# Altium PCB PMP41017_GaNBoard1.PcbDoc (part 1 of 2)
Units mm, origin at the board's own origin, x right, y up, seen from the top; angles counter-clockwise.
Board outline 21.11 x 35.1 mm, 4 copper layers (Top Layer, Layer 1, Layer 2, Bottom Layer), stack 1.926 mm thick; 24 components, 34 nets, 167 pads, 758 vias.
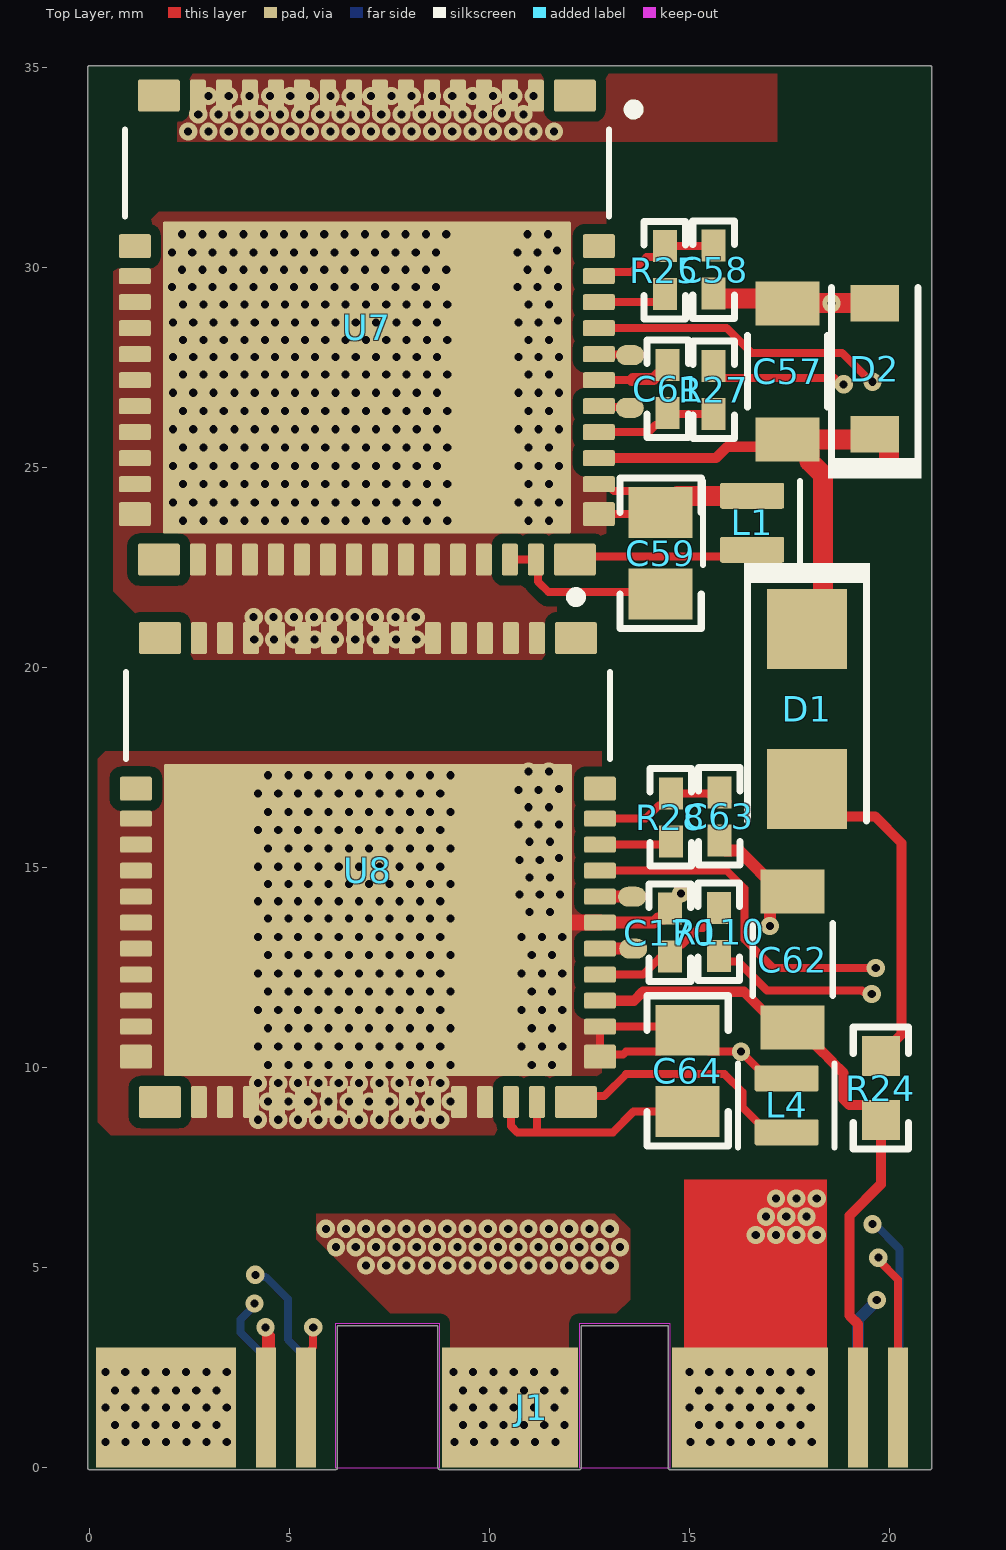
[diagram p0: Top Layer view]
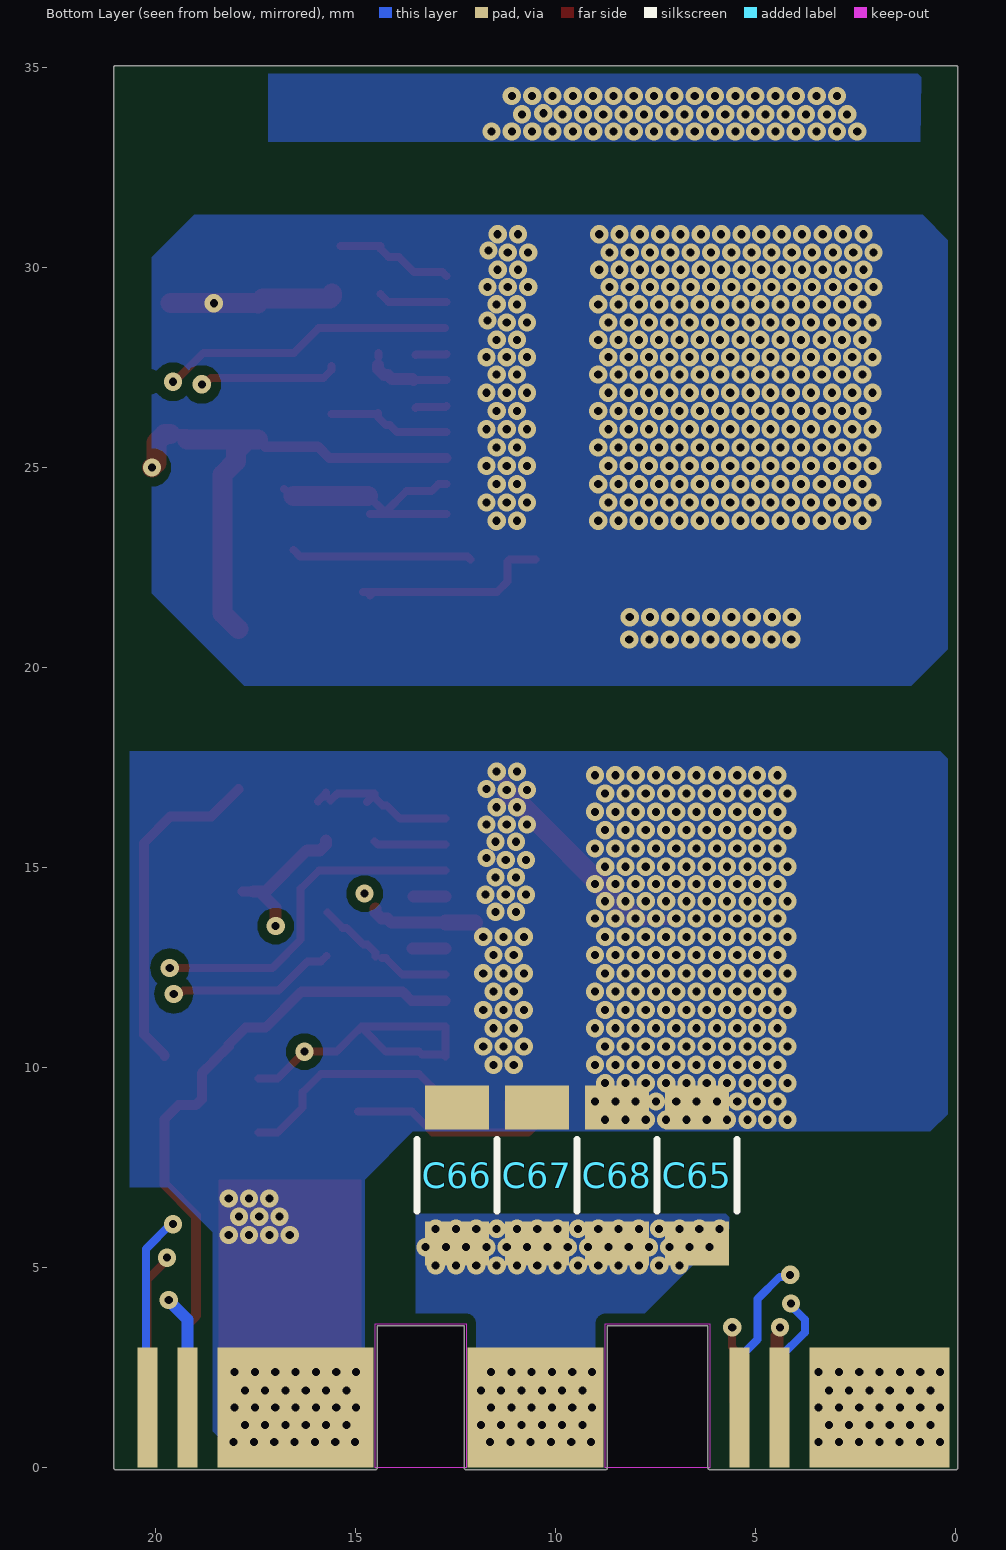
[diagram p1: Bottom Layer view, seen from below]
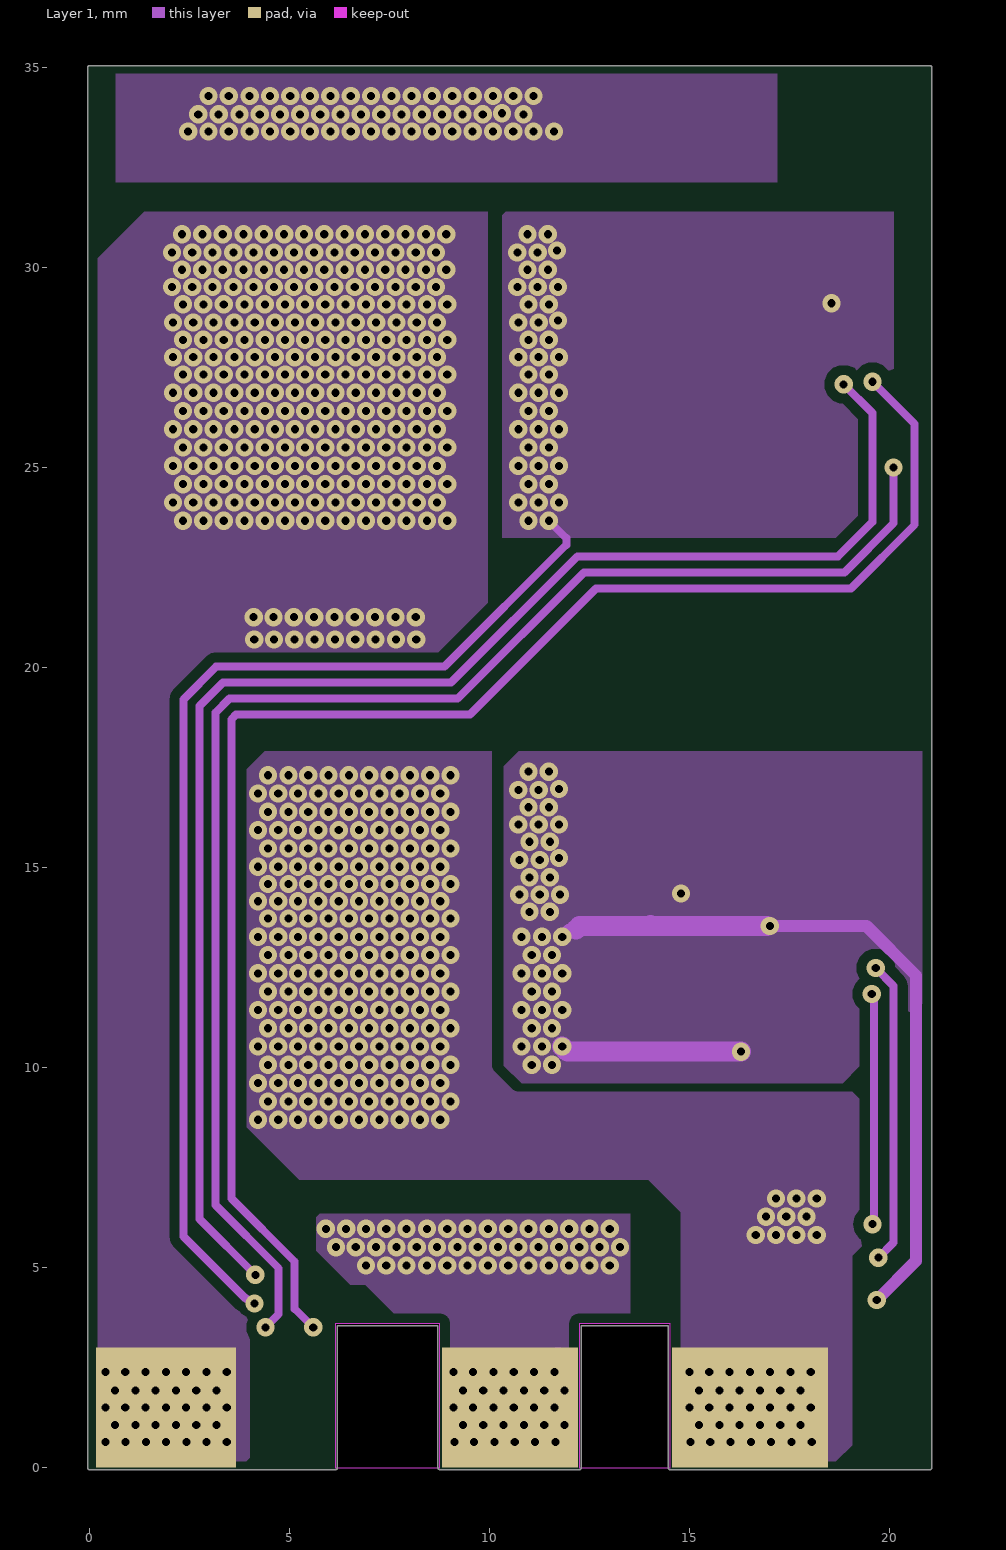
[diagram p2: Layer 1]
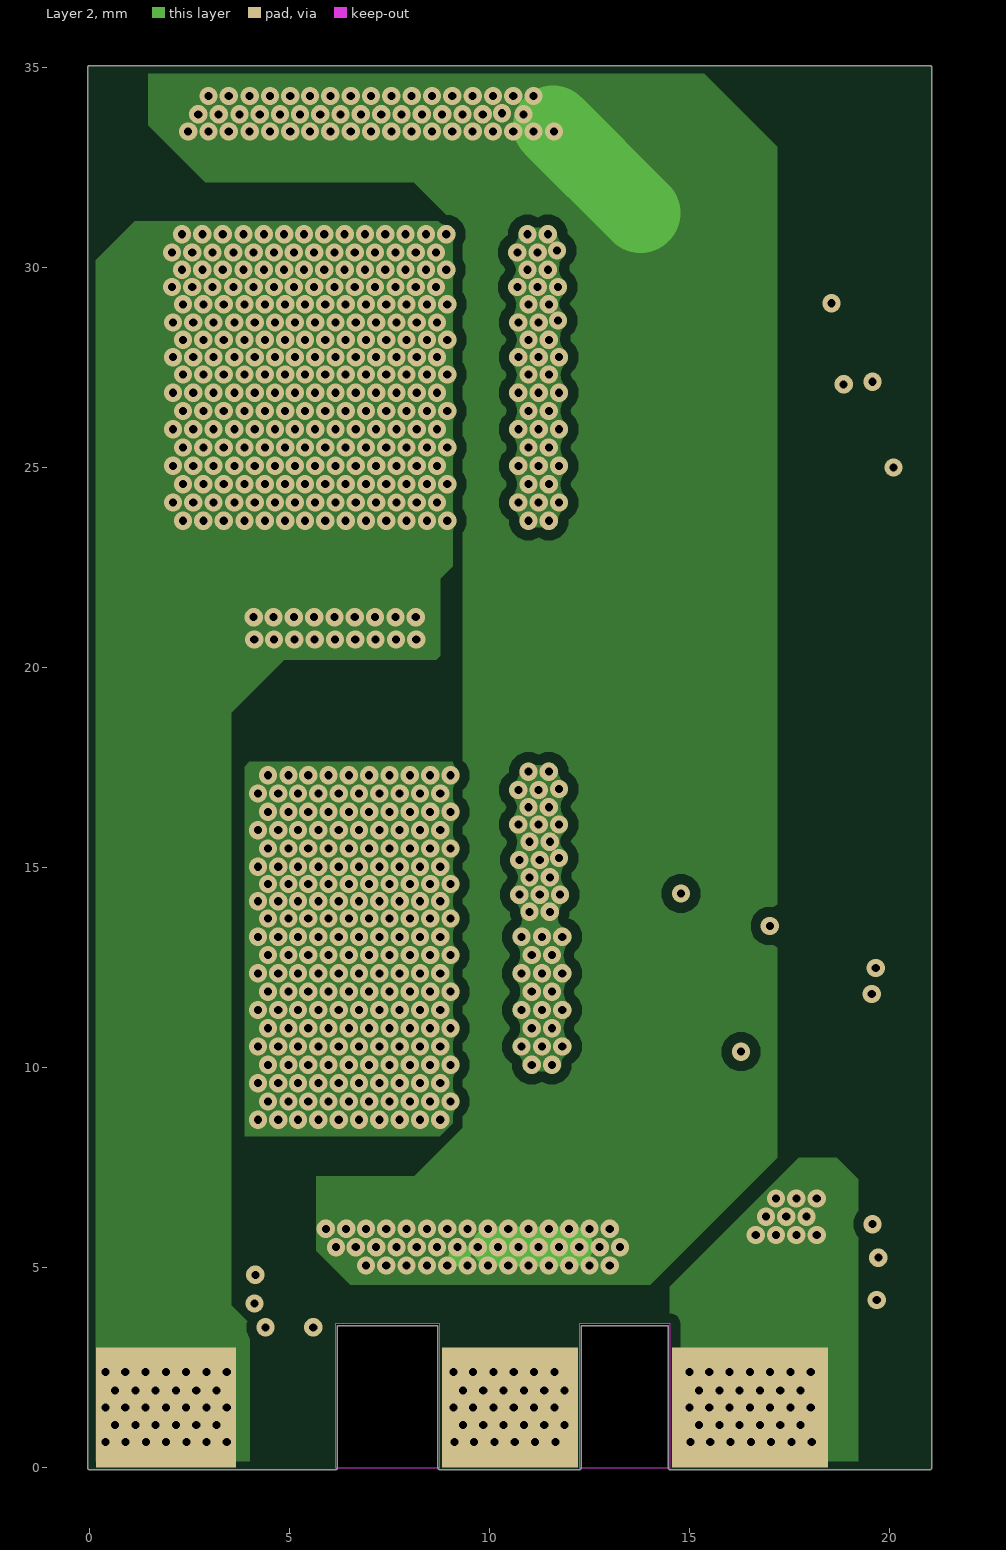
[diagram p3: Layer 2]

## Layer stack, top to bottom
Top Solder: solder mask 0.0102, Solder Resist, Dk 3.5
Top Layer: signal copper 0.07
Dielectric 1: prepreg 0.0711, PP-006, Dk 4.1
Layer 1: signal copper 0.07
Dielectric1: core 1.5037, FR-4 High Tg, Dk 4.8
Layer 2: signal copper 0.07
Dielectric 2: prepreg 0.0711, PP-006, Dk 4.1
Bottom Layer: signal copper 0.07
Bottom Solder: solder mask 0.0102, Solder Resist, Dk 3.5

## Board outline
21.055,0 21.055,34.999 ccw(c21.005,35) 21.005,35.05 0,35.05 ccw(c0,35) -0.05,35 -0.05,0 ccw(c0,0) 0.002,-0.05 6.146,-0.05 ccw(c6.146,0) 6.196,0 6.196,3.55 8.708,3.55 8.708,0 ccw(c8.759,0) 8.759,-0.05 12.242,-0.05 ccw(c12.242,0) 12.292,0 12.292,3.55 14.464,3.55 14.464,0 ccw(c14.514,0) 14.514,-0.05 21.005,-0.05 ccw(c21.005,0)
cut-out: 8.759,0 8.759,3.6 6.146,3.6 6.146,0
cut-out: 14.514,0 14.514,3.6 12.242,3.6 12.242,0

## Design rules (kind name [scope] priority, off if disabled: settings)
AcuteAngle [All] p1: minimum=4.50000000000000E+0001 checktracksonly=FALSE
AssemblyTestPointUsage [All] p1: valid=2
BoardOutlineClearance BoardOutlineClearance_MountingHoles [OnCopper and InComponentClass('Mounting Holes')] p1: gap=0.2 ignorepadtopadclearanceinfootprint=FALSE
BoardOutlineClearance BoardOutlineClearance_Poly [OnCopper and IsPoly] p2: gap=0.2 ignorepadtopadclearanceinfootprint=FALSE
BoardOutlineClearance [OnCopper and Not InComponentClass('Logo') and not InComponentClass('FiducialMark') and not InRegion(1000,500,4000,800) and not InPoly] p3: gap=0.2 ignorepadtopadclearanceinfootprint=FALSE
Clearance Clearance_Keepouts [((IsTrack Or IsArc) And Not InPoly) And IsFree and IsKeepOut vs ((IsTrack Or IsArc) And Not InPoly) And IsFree and IsKeepOut] p1: gap=0 ignorepadtopadclearanceinfootprint=FALSE
Clearance Clearance_Poly [InPolygon] p2: gap=0.254 ignorepadtopadclearanceinfootprint=TRUE
Clearance Clearance_FiducialMark [IsKeepOut and InComponentClass('FiducialMark') vs IsPad and InComponentClass('FiducialMark')] p3: gap=0 ignorepadtopadclearanceinfootprint=FALSE
Clearance [All] p4: gap=0.2 ignorepadtopadclearanceinfootprint=TRUE
ComponentClearance ComponentClearance_MountingHoles_FiducialMarks [InComponentClass('Mounting Holes') vs InComponentClass('FiducialMark')] p1 off: gap=1.27 collisioncheckmode=3 verticalgap=0.254 showdistances=FALSE
ComponentClearance ComponentClearance_Shunt [InComponentClass('Header') vs InComponentClass('Shunt')] p2 off: gap=0 collisioncheckmode=3 verticalgap=0 showdistances=FALSE
ComponentClearance ComponentClearance_Logo [InComponentClass('Logo')] p3 off: gap=0.762 collisioncheckmode=3 verticalgap=0.254 showdistances=FALSE
ComponentClearance ComponentClearance_ScrewToNut [(HasFootprint('NY PMS 440 0025 PH')) vs (HasFootprint('Keystone_1902C'))] p4 off: gap=0.127 collisioncheckmode=3 verticalgap=0.254 showdistances=FALSE
ComponentClearance ComponentClearance_MountingHoles [InComponentClass('Mounting Holes')] p5 off: gap=2.54 collisioncheckmode=3 verticalgap=2540 showdistances=FALSE
ComponentClearance ComponentClearance_SmallPassives [HasFootprint('0201*') or HasFootprint('0402*') or HasFootprint('0508') or HasFootprint('0603*') or HasFootprint('0612') or HasFootprint('0805*') or HasFootprint('0815*') or HasFootprint('0830*') or HasFootprint('1206*') or HasFootprint('1210*') or HasFootprint('1808*') or HasFootprint('1812*') or HasFootprint('1825*') or HasFootprint('2010*') or HasFootprint('2220*') or HasFootprint('2225*') or HasFootprint('2512*') or HasFootprint('2728*') or HasFootprint('3518*') vs HasFootprint('0201*') or HasFootprint('0402*') or HasFootprint('0508') or HasFootprint('0603*') or HasFootprint('0612') or HasFootprint('0805*') or HasFootprint('0815*') or HasFootprint('0830*') or HasFootprint('1206*') or HasFootprint('1210*') or HasFootprint('1808*') or HasFootprint('1812*') or HasFootprint('1825*') or HasFootprint('2010*') or HasFootprint('2220*') or HasFootprint('2225*') or HasFootprint('2512*') or HasFootprint('2728*') or HasFootprint('3518*')] p6 off: gap=0.38 collisioncheckmode=3 verticalgap=0.254 showdistances=FALSE
ComponentClearance ComponentClearance_THtoSMT [IsThruComponent vs IsSMTComponent] p7 off: gap=0.762 collisioncheckmode=3 verticalgap=0.762 showdistances=FALSE
ComponentClearance ComponentClearance_THtoTH [IsThruComponent vs IsThruComponent] p8 off: gap=0.508 collisioncheckmode=3 verticalgap=0.762 showdistances=FALSE
ComponentClearance [All] p9 off: gap=0.508 collisioncheckmode=3 verticalgap=0.254 showdistances=FALSE
DiffPairsRouting [All] p1: maxlimit=2.54 minlimit=0.254 mostfreqgap=0.254 toplayer_minwidth=0.381 toplayer_maxwidth=0.381 toplayer_prefwidth=0.381 midlayer1_minwidth=0.381 midlayer1_maxwidth=0.381 midlayer1_prefwidth=0.381 midlayer2_minwidth=0.381 midlayer2_maxwidth=0.381 midlayer2_prefwidth=0.381 bottomlayer_minwidth=0.381 bottomlayer_maxwidth=0.381 bottomlayer_prefwidth=0.381 maxuncoupledlength=25.4
FabricationTestPointUsage TestPointUsage [All] p1: valid=2 allowmultiple=FALSE
FabricationTestpoint Testpoint [All] p1: side=3 testpointundercomponent=TRUE minsize=1.016 maxsize=2.54 preferedsize=1.524 minholesize=0 maxholesize=1.016 preferedholesize=0.813 testpointgrid=0.025 allowsidetop=TRUE allowsidebottom=TRUE usegrid=TRUE gridtolerance=0
FanoutControl Fanout_LCC [IsLCC] p1: bgadir=Out bgaviamode=Centered fanoutstyle=Auto fanoutdirection=Alternating viagrid=0.025 // Fanout_LCC (Default Rule)
FanoutControl Fanout_BGA [IsBGA] p2: bgadir=Out bgaviamode=Centered fanoutstyle=Auto fanoutdirection=Alternating viagrid=0.025 // Fanout_BGA (Default Rule)
FanoutControl Fanout_Default [All] p4: bgadir=Out bgaviamode=Centered fanoutstyle=Auto fanoutdirection=Alternating viagrid=0.025 // Fanout_Default (Default Rule)
FanoutControl Fanout_Small [(CompPinCount < 5)] p5: bgadir=Out bgaviamode=Centered fanoutstyle=Auto fanoutdirection=OutThenIn viagrid=0.025 // Fanout_Small (Default Rule)
Height [All] p1 off: minheight=0 maxheight=30 prefheight=12.7
HoleSize [All] p1: absolutevalues=TRUE maxlimit=6.375 minlimit=0.2 maxpercent=80.000 minpercent=20.000
MinimumAnnularRing MinimumAnnularRing_ThermalPadVias [IsVia and InAnyComponent] p1: minimumring=0.15
MinimumAnnularRing [All] p2: minimumring=0.125
MinimumSolderMaskSliver MinimumSolderMaskSliver_Logo [InComponentClass('Logo') vs InComponentClass('Logo')] p1: minsoldermaskwidth=0.018
MinimumSolderMaskSliver [All] p2: minsoldermaskwidth=0.1
PlaneConnect [All] p1: planeconnectstyle=Relief reliefexpansion=0.254 reliefentries=4 reliefconductorwidth=0.254 reliefairgap=0.254
PolygonConnect [All] p1: connectstyle=Direct reliefconductorwidth=0.254 reliefentries=4 polygonreliefangle="90 Angle" airgapwidth=0.254
RoutingVias ThermalPadVias [IsVia and InAnyComponent] p1: holewidth=0.2 width=0.5 viastyle="Through Hole" minholewidth=0.2 minwidth=0.5 maxholewidth=0.33 maxwidth=0.6
RoutingVias [All] p2: holewidth=0.3 width=0.5 viastyle="Through Hole" minholewidth=0.2 minwidth=0.45 maxholewidth=1.016 maxwidth=1.651
SilkToBoardRegionClearance [Not ((IsComment or IsDesignator) And (Hide <> 'False')) and not InRegion(1000,500,4000,800)] p1:
SilkToSilkClearance SilkToSilkClearance_Pb-FreeLogo [(HasFootprint('Pb-Free_Overlay_Medium') OR HasFootprint('Pb-Free_Overlay_Small')) vs (HasFootprint('Pb-Free_Overlay_Medium') OR HasFootprint('Pb-Free_Overlay_Small'))] p1: silktosilkclearance=0
SilkToSilkClearance [All] p2: silktosilkclearance=0.1
SilkToSolderMaskClearance SilkToComponentPadClearance [(IsPad or IsFill or IsRegion) and InAnycomponent] p1: minsilkscreentomaskgap=0.127 clearancetoexposedcopper=TRUE
SilkToSolderMaskClearance "Silk to Solder Mask Opening" [All] p2: minsilkscreentomaskgap=0.1 clearancetoexposedcopper=FALSE
SolderMaskExpansion [All] p1: expansion=0.05 istentingtop=FALSE
UnRoutedNet [All] p1: checkbadconnections=TRUE
Width [All] p1: maxlimit=2.54 minlimit=0.152 preferedwidth=0.254 checkconnectedcopper=TRUE
13 further rules are at their usual default settings.

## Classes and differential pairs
net class VSWNET: 5V_H FAULT_H INH ISO_12V_H NetC61_2 NetL1_2 OC_H RDRV_H SW TEMP_H U1NC17 U1NC28 U1NC54 U2NC1 U2NC16 VNEG_H
net class VHV: HVBUS U1NC1 U1NC16
net class PGND: 5V_L FAULT_L INL ISO_12V_L NetC170_2 NetD1_2 NetL4_2 NetR28_1 OC_L PGND TEMP_L U2NC17 U2NC28 U2NC54 VNEG_L

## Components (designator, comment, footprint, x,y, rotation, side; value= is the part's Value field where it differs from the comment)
C57 "C1206C106K3RACTU" 1206_190 17.449,27.408 r90 top value=10uF
C58 "CL05B224KO5NNNC" 0402 15.599,29.951 r270 top value=0.22uF
C59 "GRM219R61E225KA12D" 0805_HV 14.274,22.86 r90 top value=2.2uF
C61 "C1005C0G1H220J050BA" 0402 14.45,26.969 r270 top value=22pF
C62 "C1206C106K3RACTU" 1206_190 17.576,12.7 r270 top value=10uF
C63 "CL05B224KO5NNNC" 0402 15.743,16.281 r270 top value=0.22uF
C64 "GRM219R61E225KA12D" 0805_HV 14.95,9.918 r90 top value=2.2uF
C65 "C1206C223KDRACTU" 1206_190 6.47,7.308 r90 bottom value=0.022uF
C66 "C1206C223KDRACTU" 1206_190 12.468,7.308 r90 bottom value=0.022uF
C67 "C1206C223KDRACTU" 1206_190 10.469,7.308 r90 bottom value=0.022uF
C68 "C1206C223KDRACTU" 1206_190 8.469,7.308 r90 bottom value=0.022uF
C170 "C1005C0G1H220J050BA" 0402 14.506,13.373 r270 top value=22pF
D1 "US1M-13-F" SMA 17.935,18.961 r270 top value=1000V
D2 "BZT52C16-7-F" SOD-123 19.628,27.474 r90 top value=16V
J1 "Edge Finger" EC_GAN_DC_HBLLC 21.005,4 r180 top
L1 "SDEM20161T-4R7MS" FP-SDEM20161T-4R7MS_SMD2-MFG 16.56,23.622 r270 top
L4 "SDEM20161T-4R7MS" FP-SDEM20161T-4R7MS_SMD2-MFG 17.427,9.055 r270 top
R24 "MCT06030C2008FP500" 0603 19.78,9.489 r270 top value=2.00
R25 "MCR01MZPJ000" 0402 14.379,29.937 r90 top value=0
R27 "CRCW0402300RJNED" 0402 15.603,26.946 r270 top value=300
R28 "MCR01MZPJ000" 0402 14.528,16.256 r90 top value=0
R110 "CRCW0402300RJNED" 0402 15.728,13.397 r90 top value=300
U7 "LMG3425R030RQZT" RQZ0054A-MFG-NV 6.93,28.502 r270 top
U8 "LMG3425R030RQZT" RQZ0054A-MFG-NV 6.957,14.939 r270 top

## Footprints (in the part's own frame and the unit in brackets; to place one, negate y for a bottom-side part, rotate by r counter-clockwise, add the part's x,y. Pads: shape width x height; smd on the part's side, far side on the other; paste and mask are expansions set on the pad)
0402 [mm] "0402 from SM-752 data"
  rect 0.8x0.6 smd: 1(-0.6,0) 2(0.6,0)
  silkscreen extent -1.22,-0.52 1.22,0.52, body extent -0.55,-0.3 0.55,0.3, height 0.6
0603 [mm] "0603 from SM-752 data"
  rect 1x0.95 smd: 1(-0.8,0) 2(0.8,0)
  silkscreen extent -1.52,-0.69 1.52,0.69, body extent -0.87,-0.47 0.87,0.47, height 1
0805_HV [mil] "0805 with 30mil clearance between pads"
  rect 50x63 smd: 1(-40,0) 2(40,0)
  silkscreen extent -74,-40 74,40, body extent -43,-29 43,29, height 57
1206_190 [mm] "1206_190"
  rect 1.1x1.6 smd: 1(-1.7,0) 2(1.7,0)
  silkscreen extent -0.9,-1 0.9,1, body extent -1.75,-0.95 1.75,0.95, height 1.9
EC_GAN_DC_HBLLC [mm] "Edge connector of HB LLC GaN DC"
  rect 0.5x3 smd: 1(0.8,2.5) 3(1.8,2.5) 5(15.6,2.5) 7(16.6,2.5)
  rect 0.5x3 smd far side: 2(0.8,2.5) 4(1.8,2.5) 6(15.6,2.5) 8(16.6,2.5)
  rect 3.4x3 all layers, no hole: HV(10.5,2.5)
  rect 3.9x3 all layers, no hole: PG(4.5,2.5)
  rect 3.5x3 all layers, no hole: SW(19.1,2.5)
FP-SDEM20161T-4R7MS_SMD2-MFG [mm]
  rrect15% 0.65x1.6 smd paste+0 mask+0: 1(-0.675,0) 2(0.675,0)
  silkscreen extent -1.05,-1.22 1.05,1.2, body extent -1,-0.8 1,0.8, height 1
RQZ0054A-MFG-NV [mm]
  rrect13% 0.8x1.05 smd paste+0 mask+0: 1(-5.8,5.2) 16(-5.8,-5.2) 28(5.8,-5.2) 43(5.8,5.2)
  rrect25% 0.8x0.4 smd paste+0 mask+0: 2(-5.8,4.225) 3(-5.8,3.575) 4(-5.8,2.925) 5(-5.8,2.275) 6(-5.8,1.625) 7(-5.8,0.975) 8(-5.8,0.325) 9(-5.8,-0.325) 10(-5.8,-0.975) 11(-5.8,-1.625) 12(-5.8,-2.275) 13(-5.8,-2.925) 14(-5.8,-3.575) 15(-5.8,-4.225) 29(5.8,-4.225) 30(5.8,-3.575) 31(5.8,-2.925) 32(5.8,-2.275) 33(5.8,-1.625) 34(5.8,-0.975) 35(5.8,-0.325) 36(5.8,0.325) 37(5.8,0.975) 38(5.8,1.625) 39(5.8,2.275) 40(5.8,2.925) 41(5.8,3.575) 42(5.8,4.225)
  rrect17% 0.6x0.8 smd paste+0 mask+0: 17(-2.035,-5.8) 27(4.665,-5.8) 44(4.665,5.8) 54(-2.035,5.8)
  rrect25% 0.4x0.8 smd paste+0 mask+0: 18(-1.285,-5.8) 19(-0.635,-5.8) 20(0.015,-5.8) 21(0.665,-5.8) 22(1.315,-5.8) 23(1.965,-5.8) 24(2.615,-5.8) 25(3.265,-5.8) 26(3.915,-5.8) 45(3.915,5.8) 46(3.265,5.8) 47(2.615,5.8) 48(1.965,5.8) 49(1.315,5.8) 50(0.665,5.8) 51(0.015,5.8) 52(-0.635,5.8) 53(-1.285,5.8)
  rrect1% 7.8x10.2 smd paste-1000 mask+0: 55(1.25,0)
  silkscreen extent -5.58,-6.05 -2.78,6.8, body extent -6,-6 6,6, height 0.9
SMA [mm] "Molded Diode, 2-Leads, Body 4.3x2.6mm, IPC Medium Density, based on OnSemi component dimensions and land pattern"
  rect 2x2 smd: 1(-2,0) 2(2,0)
  silkscreen extent -3.66,-1.57 2.79,1.57, body extent -2.6,-1.3 2.6,1.3, height 2.42
SOD-123 [mm] "On Semi recommended land pattern"
  rect 0.915x1.22 smd: 1(-1.637,0) 2(1.637,0)
  silkscreen extent -2.74,-1.17 2.03,1.17, body extent -1.93,-0.9 1.93,0.9, height 1.35

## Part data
C57 C62: library part CMP-0008589-2, "CAP, CERM, 10 uF, 25 V, +/- 10%, X7R, 1206_190", Cap_Case=1206, Manufacturer=Kemet, Supplier Part Number 1=399-7442-1-ND, TempCo=X7R, Tolerance_%=10%, Value1=Unknown, Value2=25V, ValueDisplayed=10uF
C58 C63: library part CMP-0860563-1, "CAP, CERM, 0.22 µF, 16 V,+/- 10%, X7R, 0402", Cap_Case=0402, Manufacturer="Samsung Electro-Mechanics", TempCo=X7R, Tolerance_%=10%, Value2=16V, ValueDisplayed=0.22µF
C59 C64: library part CMP-0008208-1, "CAP, CERM, 2.2 uF, 25 V, +/- 10%, X5R, 0805", Cap_Case=0805, Manufacturer=MuRata, Supplier Part Number 1=490-1701-1-ND, TempCo=X5R, Tolerance_%=10%, Value1="0.006 ohm", Value2=25V, ValueDisplayed=2.2uF
C61 C170: library part CMP-0006248-2, "CAP, CERM, 22 pF, 50 V, +/- 5%, C0G/NP0, 0402", Alternate Manufacturer=TDK, Alternate PartNumber=CGA2B2NP01H220J050BA, Cap_Case=0402, Supplier Part Number 1=445-1239-1-ND, TempCo=C0G/NP0, Tolerance_%=5%, Value1=Unknown, Value2=50V, ValueDisplayed=22pF
C65 C66 C67 C68: library part CMP-0084048-1, "CAP, CERM, 0.022 µF, 1000 V,+/- 10%, X7R, AEC-Q200 Grade 1, 1206", Cap_Case=1206, Manufacturer=Kemet, TempCo=X7R, Tolerance_%=10%, Value2=1000V, ValueDisplayed=0.022µF
D1: library part CMP-0076882-1, "Diode, Ultrafast, 1000 V, 1 A, SMA", Manufacturer="Diodes Inc.", Supplier Part Number 1=US1M-FDICT-ND, Value1=1A, Value2=1.7V
D2: library part CMP-0005769-2, "Diode, Zener, 16 V, 500 mW, AEC-Q101, SOD-123", Manufacturer="Diodes Inc.", Power_W=500mW, Supplier Part Number 1=BZT52C16-FDICT-ND, Value1=0.5W
J1: library part EC_GaN
L1 L4: library part CMP-0089347-1, "4.7µH Unshielded Inductor 1.1A 426mOhm Max 0806 (2016 Metric)", Digikey Part Number=2037-SDEM20161T-4R7MSCT-ND, Manufacturer=Cyntec, Operating Temperature Range="-55°C to +125°C", Test Frequency=1MHz, Tolerance_%=20%
R24: library part CMP-0022732-2, "RES, 2.00, 1%, 0.125 W, 0603", Manufacturer=Vishay/Beyschlag, Power_W=125mW, Supplier Part Number 1=MCT06030C2008FP500-ND, TempCo="50 ppm/C", Tolerance_%=1%, Value2=0.125W, Value_Code=2R00, ValueDisplayed=2.00
R25 R28: library part CMP-0027002-2, "RES, 0, 5%, 0.063 W, 0402", Manufacturer=Rohm, Power_W=63mW, Supplier Part Number 1=RHM0.0JCT-ND, TempCo="500 ppm/C", Tolerance_%=5%, Value2=0.063W, Value_Code=0000, ValueDisplayed=0
R27 R110: library part CMP-0026902-3, "RES, 300, 5%, 0.063 W, AEC-Q200 Grade 0, 0402", Manufacturer=Vishay-Dale, Power_W=63mW, Supplier Part Number 1=541-300JCT-ND, TempCo="200 ppm/C", Tolerance_%=5%, Value2=0.063W, Value_Code=300R, ValueDisplayed=300
U7 U8: library part CMP-0088545-3, "600-V 30-mΩ Integrated GaN Power Stage with Smart Driver", Manufacturer="Texas Instruments", Max Supply Voltage=18V, Min Supply Voltage=7.5V, Nominal Supply Current=13mA, Operating Temperature Range="-40°C to +125°C", Output Voltage=480V

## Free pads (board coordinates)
  oval 0.7x0.5 smd: 5(13.504,26.493) 5(13.512,27.813) 5(13.562,14.273) 5(13.588,12.974)

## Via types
v1: diameter 0.457, hole 0.203, Top Layer to Bottom Layer, tented both sides, 758 vias

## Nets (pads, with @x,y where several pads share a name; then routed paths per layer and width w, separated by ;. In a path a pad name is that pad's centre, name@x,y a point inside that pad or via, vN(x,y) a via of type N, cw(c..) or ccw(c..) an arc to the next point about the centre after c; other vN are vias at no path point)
5V_H: C58.1 R25.2 U7.53 | length 3
  Top Layer w0.2: U7.53@12.73,29.787 12.83,29.887 13.548,29.887 13.927,30.265 14.179,30.265 14.379,30.465 R25.2@14.379,30.537 C58.1@15.385,30.537
5V_L: C63.1 R28.2 U8.53 | length 3.9
  Top Layer w0.2: U8.53@12.757,16.224 13.896,16.224 14.228,16.556 14.328,16.556 14.528,16.756 R28.2@14.528,16.834 ; R28.2@14.722,16.64 R28.2@14.528,16.834 ; C63.1@15.637,16.679 15.46,16.856 R28.2@14.528,16.856 R28.2@14.528,16.834 ; C63.1@15.743,16.781 C63.1@15.743,16.859 ; C63.1@15.743,16.881 C63.1@15.743,16.859 ; C63.1@15.943,16.659 C63.1@15.743,16.859
FAULT_H: pad.5@13.504,26.493 U7.48 | length 0.8
  Top Layer w0.2: U7.48@12.73,26.537 12.752,26.515 13.483,26.515 pad.5@13.504,26.493
FAULT_L: pad.5@13.588,12.974 U8.48 | length 0.8
  Top Layer w0.3: U8.48@12.757,12.974 pad.5@13.588,12.974
HVBUS: C65.1 C66.1 C67.1 C68.1 J1.HV U7.2 U7.3 U7.4 U7.5 U7.6 U7.7 U7.8 U7.9 U7.10 U7.11 U7.12 U7.13 U7.14 U7.15 | length 6.7
  Layer 1 w1: J1.HV@10.505,1.5 10.705,1.5 J1.HV@11.705,2.5
  Layer 2 w0.5: 9.216,5.276 v1@9.286,5.347
  Layer 2 w1: v1@10.061,5.53 v1@10.315,5.53 ; v1@10.569,5.53 v1@10.823,5.53 ; v1@11.064,5.53 v1@11.318,5.53 ; v1(11.099,33.401) 11.353,33.401 ; v1@11.2,33.553 v1@11.581,33.553 ; v1@11.572,5.53 v1@12.08,5.53
  Layer 2 w2: v1@11.581,33.553 13.766,31.369
  other v1: 9.118,0.636 9.613,0.636 10.121,0.636 10.629,0.636 11.137,0.636 11.645,0.636 9.334,1.068 9.842,1.068 10.35,1.068 10.858,1.068 11.366,1.068 11.874,1.068 9.093,1.5 9.588,1.5 10.096,1.5 10.604,1.5 11.112,1.5 11.62,1.5 9.334,1.932 9.842,1.932 10.35,1.932 10.858,1.932 11.366,1.932 11.874,1.932 9.093,2.389 9.588,2.389 10.096,2.389 10.604,2.389 11.112,2.389 11.62,2.389 6.908,5.055 7.416,5.055 7.924,5.055 8.432,5.055 8.94,5.055 9.448,5.055 9.956,5.055 10.464,5.055 10.972,5.055 11.48,5.055 11.988,5.055 12.496,5.055 13.004,5.055 6.159,5.512 6.654,5.512 7.162,5.512 7.67,5.512 8.178,5.512 8.686,5.512 9.194,5.512 9.702,5.512 10.21,5.512 10.718,5.512 11.226,5.512 11.734,5.512 12.242,5.512 12.75,5.512 13.258,5.512 5.905,5.969 6.413,5.969 6.908,5.969 7.416,5.969 7.924,5.969 8.432,5.969 8.94,5.969 9.448,5.969 9.956,5.969 10.464,5.969 10.972,5.969 11.48,5.969 11.988,5.969 12.496,5.969 13.004,5.969 2.463,33.401 2.971,33.401 3.479,33.401 4,33.401 4.508,33.401 5.016,33.401 5.511,33.401 6.019,33.401 6.527,33.401 7.035,33.401 7.543,33.401 8.051,33.401 8.559,33.401 9.067,33.401 9.575,33.401 10.083,33.401 10.591,33.401 11.607,33.401 2.717,33.833 3.225,33.833 3.746,33.833 4.254,33.833 4.762,33.833 5.257,33.833 5.765,33.833 6.273,33.833 6.781,33.833 7.289,33.833 7.797,33.833 8.305,33.833 8.813,33.833 9.321,33.833 9.829,33.833 10.845,33.833 10.311,33.858 2.971,34.29 3.479,34.29 4,34.29 4.508,34.29 5.016,34.29 5.511,34.29 6.019,34.29 6.527,34.29 7.035,34.29 7.543,34.29 8.051,34.29 8.559,34.29 9.067,34.29 9.575,34.29 10.083,34.29 10.591,34.29 11.099,34.29
INH: J1.6 R27.1 | length 44.7
  Top Layer w0.2: R27.1@15.603,27.546 15.603,27.446 15.803,27.246 18.617,27.246 18.78,27.082 v1(18.849,27.082)
  Layer 1 w0.2: v1(4.143,4.82) 2.745,6.218 2.745,19.04 3.331,19.626 9.036,19.626 12.192,22.782 18.704,22.782 19.569,23.647 19.569,26.363 v1(18.849,27.082)
  Bottom Layer w0.2: v1(4.143,4.82) 4.192,4.771 4.401,4.771 4.955,4.217 4.955,3.2 5.255,2.9 5.405,2.75 J1.6@5.405,1.5
INL: J1.2 R110.1 | length 14.9
  Top Layer w0.2: R110.1@15.728,12.797 15.876,12.65 16.211,12.65 16.934,11.927 19.306,11.927 19.341,11.891 19.502,11.891 v1(19.552,11.842)
  Layer 1 w0.2: v1(19.552,11.842) 19.552,11.772 19.606,11.718 19.606,6.123 v1(19.571,6.087)
  Bottom Layer w0.2: v1(19.571,6.087) 19.628,6.087 20.247,5.468 20.247,1.542 J1.2@20.205,1.5
ISO_12V_H: C57.1 D1.1 D2.1 J1.7 U7.46 | length 53.8
  Top Layer w0.2: v1(4.395,3.507) 4.395,3.438 4.528,3.305 4.528,1.623 J1.7@4.405,1.5 4.405,3.26 v1@4.486,3.341
  Top Layer w0.254: U7.46@12.73,25.237 15.657,25.237 15.943,25.524 17.265,25.524 C57.1@17.449,25.708 ; D2.1@19.218,25.837 D2.1@19.628,25.837
  Top Layer w0.5: C57.1@17.449,25.708 C57.1@17.699,25.708 ; D1.1@17.935,20.961 18.33,21.356 18.33,24.827 17.999,25.158 17.999,25.408 C57.1@17.699,25.708 ; D2.1@19.218,25.708 C57.1@17.699,25.708 ; D2.1@19.628,25.837 19.78,25.837 19.988,25.629 19.988,25.114 v1(20.097,25.005)
  Layer 1 w0.2: v1(4.395,3.507) 4.727,3.839 4.727,4.984 3.145,6.565 3.145,18.874 3.497,19.226 9.201,19.226 12.358,22.382 18.87,22.382 20.097,23.61 v1(20.097,25.005)
ISO_12V_L: C62.2 J1.3 R24.2 U8.46 | length 16.5
  Top Layer w0.254: U8.46@12.757,11.674 13.608,11.674 13.83,11.896 16.361,11.896 17.255,11.002 17.755,11.002 18.178,10.579 18.178,10.531 18.327,10.382 18.334,10.382 18.554,10.162 18.554,10.155 18.849,9.859 18.849,9.211 18.998,9.062 19.432,9.062 19.78,8.714 R24.2@19.78,8.689 19.78,7.082 18.998,6.3 18.998,3.8 19.205,3.594 J1.3@19.205,1.5
NetC61_2: C61.2 R27.2 U7.47 | length 3.1
  Top Layer w0.2: U7.47@12.73,25.887 13.968,25.887 14.15,26.069 14.25,26.069 14.45,26.269 C61.2@14.45,26.369 14.474,26.346 R27.2@15.603,26.346
NetC170_2: C170.2 R110.2 U8.47 | length 3.5
  Top Layer w0.2: U8.47@12.757,12.324 13.837,12.324 14.25,12.737 C170.2@14.35,12.737 ; C170.2@14.506,12.773 14.506,12.873 14.706,13.073 14.806,13.073 15.23,13.497 15.328,13.497 R110.2@15.704,13.873
NetD1_2: D1.2 R24.1 | length 8.5
  Top Layer w0.254: D1.2@17.935,16.961 18.615,16.281 19.632,16.281 20.297,15.616 20.297,10.831 19.78,10.314 R24.1@19.78,10.289
NetL1_2: L1.2 U7.43 | length 4.5
  Top Layer w0.2: U7.43@12.13,22.702 12.21,22.782 16.395,22.782 L1.2@16.56,22.947
NetL4_2: L4.2 U8.43 | length 6.4
  Top Layer w0.2: U8.43@12.157,9.139 12.305,9.287 12.865,9.287 13.414,9.837 15.875,9.837 16.327,9.385 16.327,9.005 16.952,8.38 L4.2@17.427,8.38
NetR28_1: R28.1 U8.52 | length 1.8
  Top Layer w0.2: U8.52@12.757,15.574 14.446,15.574 R28.1@14.528,15.656
OC_H: pad.5@13.512,27.813 U7.50 | length 0.8
  Top Layer w0.2: U7.50@12.73,27.837 12.742,27.825 13.5,27.825 pad.5@13.512,27.813
OC_L: pad.5@13.562,14.273 U8.50 | length 0.8
  Top Layer w0.3: U8.50@12.757,14.274 pad.5@13.562,14.273
PGND: C62.1 C63.2 C64.2 C65.2 C66.2 C67.2 C68.2 C170.1 J1.4 J1.PG L4.1 U8.18 U8.19 U8.20 U8.21 U8.22 U8.23 U8.24 U8.25 U8.26 U8.27 U8.29 U8.30 U8.31 U8.32 U8.33 U8.34 U8.35 U8.36 U8.37 U8.38 U8.39 U8.40 U8.44 U8.45 U8.49 U8.55 | length 50.9
  Top Layer w0.2: C64.2@14.785,10.934 14.25,10.399 13.414,10.399 13.34,10.324 12.807,10.324 U8.44@12.757,10.274 U8.45@12.757,11.024 14.86,11.024 C64.2@14.95,10.934 15.485,10.399 v1(16.283,10.399) 16.952,9.73 L4.1@17.427,9.73
  Top Layer w0.254: U8.55@6.957,13.689 7.805,13.689 U8.55@11.49,17.374 ; C62.1@17.576,14.4 C62.1@17.826,14.4
  Top Layer w0.3: U8.55@7.805,13.689 8.157,13.689 U8.55@11.318,16.85 ; U8.49@12.757,13.624 14.11,13.624 14.209,13.723 14.356,13.723 14.506,13.873 C170.1@14.506,13.973 ; C63.2@15.743,15.681 15.743,15.581 15.893,15.431 16.226,15.431 C62.1@17.255,14.402 ; v1(17.005,13.538) 17.005,14 C62.1@17.405,14.4 ; C62.1@17.326,14.4 C62.1@17.405,14.4 ; C62.1@17.576,14.4 C62.1@17.405,14.4
  Top Layer w0.4: U8.55@12.02,13.624 U8.49@12.757,13.624
  Layer 1 w0.3: v1(11.815,13.27) 11.997,13.453 12.162,13.453 ; v1@16.934,13.54 19.422,13.54 20.655,12.307 20.655,5.167 v1(19.676,4.189)
  Layer 1 w0.5: v1(11.815,10.527) 11.943,10.399 v1(16.283,10.399) ; 12.162,13.453 12.249,13.54 14.031,13.54 ; 14.027,13.562 14.048,13.54 v1@16.934,13.54
  Bottom Layer w0.3: J1.4@19.205,1.5 19.205,3.7 19.676,4.172 v1(19.676,4.189)
  other v1: 15.019,0.636 15.514,0.636 16.022,0.636 16.53,0.636 17.038,0.636 17.546,0.636 18.054,0.636 15.235,1.068 15.743,1.068 16.251,1.068 16.759,1.068 17.267,1.068 17.775,1.068 14.994,1.5 15.489,1.5 15.997,1.5 16.505,1.5 17.013,1.5 17.521,1.5 18.029,1.5 15.235,1.932 15.743,1.932 16.251,1.932 16.759,1.932 17.267,1.932 17.775,1.932 14.994,2.389 15.489,2.389 15.997,2.389 16.505,2.389 17.013,2.389 17.521,2.389 18.029,2.389 16.653,5.817 17.161,5.817 17.669,5.817 18.177,5.817 16.907,6.274 17.415,6.274 17.923,6.274 17.161,6.731 17.669,6.731 18.177,6.731 4.207,8.698 4.715,8.698 5.211,8.698 5.719,8.698 6.227,8.698 6.735,8.698 7.243,8.698 7.751,8.698 8.259,8.698 8.767,8.698 4.461,9.156 4.969,9.156 5.465,9.156 5.973,9.156 6.481,9.156 6.989,9.156 7.497,9.156 8.005,9.156 8.513,9.156 9.021,9.156 4.207,9.613 4.715,9.613 5.211,9.613 5.719,9.613 6.227,9.613 6.735,9.613 7.243,9.613 7.751,9.613 8.259,9.613 8.767,9.613 4.461,10.07 4.969,10.07 5.465,10.07 5.973,10.07 6.481,10.07 6.989,10.07 7.497,10.07 8.005,10.07 8.513,10.07 9.021,10.07 11.053,10.07 11.561,10.07 4.207,10.527 4.715,10.527 5.211,10.527 5.719,10.527 6.227,10.527 6.735,10.527 7.243,10.527 7.751,10.527 8.259,10.527 8.767,10.527 10.799,10.527 11.307,10.527 4.461,10.984 4.969,10.984 5.465,10.984 5.973,10.984 6.481,10.984 6.989,10.984 7.497,10.984 8.005,10.984 8.513,10.984 9.021,10.984 11.053,10.984 11.561,10.984 4.207,11.442 4.715,11.442 5.211,11.442 5.719,11.442 6.227,11.442 6.735,11.442 7.243,11.442 7.751,11.442 8.259,11.442 8.767,11.442 10.799,11.442 11.307,11.442 11.815,11.442 4.461,11.899 4.969,11.899 5.465,11.899 5.973,11.899 6.481,11.899 6.989,11.899 7.497,11.899 8.005,11.899 8.513,11.899 9.021,11.899 11.053,11.899 11.561,11.899 4.207,12.356 4.715,12.356 5.211,12.356 5.719,12.356 6.227,12.356 6.735,12.356 7.243,12.356 7.751,12.356 8.259,12.356 8.767,12.356 10.799,12.356 11.307,12.356 11.815,12.356 4.461,12.813 4.969,12.813 5.465,12.813 5.973,12.813 6.481,12.813 6.989,12.813 7.497,12.813 8.005,12.813 8.513,12.813 9.021,12.813 11.053,12.813 11.561,12.813 4.207,13.27 4.715,13.27 5.211,13.27 5.719,13.27 6.227,13.27 6.735,13.27 7.243,13.27 7.751,13.27 8.259,13.27 8.767,13.27 10.799,13.27 11.307,13.27 4.461,13.728 4.969,13.728 5.465,13.728 5.973,13.728 6.481,13.728 6.989,13.728 7.497,13.728 8.005,13.728 8.513,13.728 9.021,13.728 10.997,13.894 11.505,13.894 4.207,14.159 4.715,14.159 5.211,14.159 5.719,14.159 6.227,14.159 6.735,14.159 7.243,14.159 7.751,14.159 8.259,14.159 8.767,14.159 10.743,14.326 11.251,14.326 11.759,14.326 14.782,14.351 4.461,14.591 4.969,14.591 5.465,14.591 5.973,14.591 6.481,14.591 6.989,14.591 7.497,14.591 8.005,14.591 8.513,14.591 9.021,14.591 10.997,14.757 11.505,14.757 4.207,15.023 4.715,15.023 5.211,15.023 5.719,15.023 6.227,15.023 6.735,15.023 7.243,15.023 7.751,15.023 8.259,15.023 8.767,15.023 10.743,15.189 11.251,15.189 11.734,15.24 4.461,15.48 4.969,15.48 5.465,15.48 5.973,15.48 6.481,15.48 6.989,15.48 7.497,15.48 8.005,15.48 8.513,15.48 9.021,15.48 10.997,15.646 11.505,15.646 4.207,15.937 4.715,15.937 5.211,15.937 5.719,15.937 6.227,15.937 6.735,15.937 7.243,15.937 7.751,15.937 8.259,15.937 8.767,15.937 10.718,16.078 11.226,16.078 11.734,16.078 4.461,16.395 4.969,16.395 5.465,16.395 5.973,16.395 6.481,16.395 6.989,16.395 7.497,16.395 8.005,16.395 8.513,16.395 9.021,16.395 10.972,16.51 11.48,16.51 4.207,16.852 4.715,16.852 5.211,16.852 5.719,16.852 6.227,16.852 6.735,16.852 7.243,16.852 7.751,16.852 8.259,16.852 8.767,16.852 10.718,16.942 11.226,16.942 11.734,16.967 4.461,17.309 4.969,17.309 5.465,17.309 5.973,17.309 6.481,17.309 6.989,17.309 7.497,17.309 8.005,17.309 8.513,17.309 9.021,17.309 10.972,17.399 11.48,17.399
RDRV_H: R25.1 U7.52 | length 1.7
  Top Layer w0.2: U7.52@12.73,29.137 14.179,29.137 R25.1@14.379,29.337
